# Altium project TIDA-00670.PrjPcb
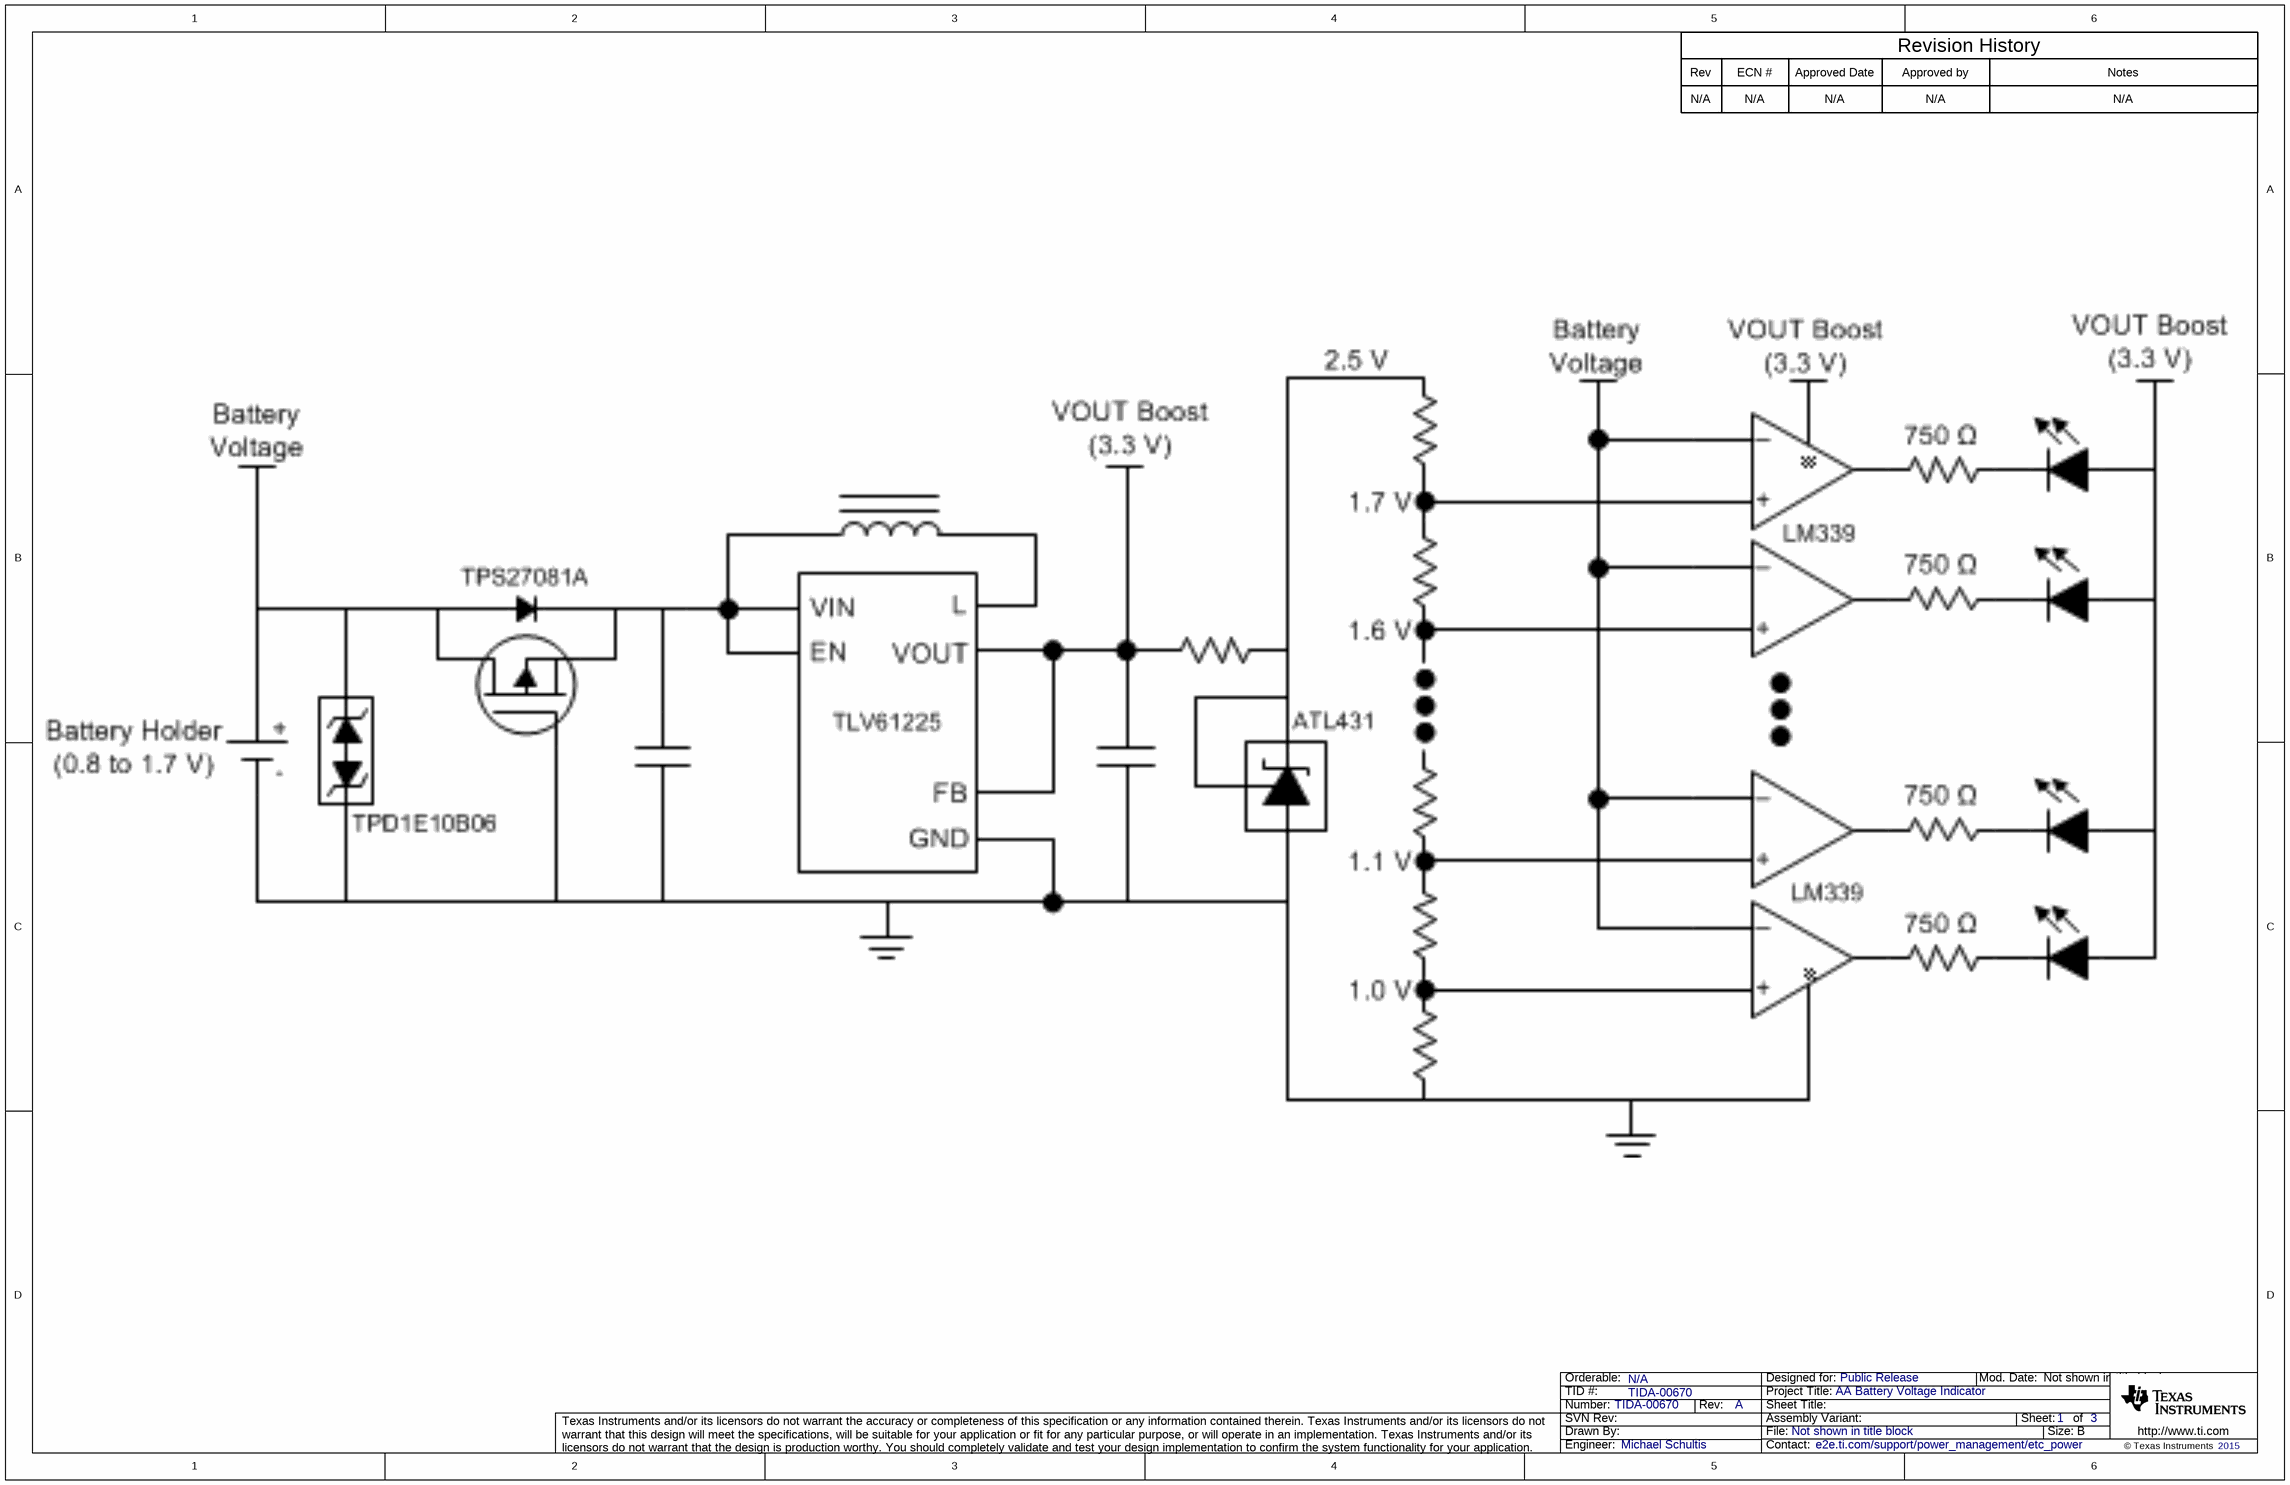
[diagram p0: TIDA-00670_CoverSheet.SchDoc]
TID: TIDA-00670; TechSupport: e2e.ti.com/support/power_management/etc_power; SCH_Rev: A; PRJ_Title: AA Battery Voltage Indicator; PRJ_Number: TIDA-00670; PRJ_Engineer: Michael Schultis; PRJ_Customer: Public Release; PCB_Rev: E1; PCB_Layout: Michael Schultis; EVM_Orderable: N/A; CopyrightYear: 2015
3 sheets, 54 parts. Net scope: global (net labels, ports and power ports of the same name join across sheets).
Board file: TIDA-00670_TID.PcbDoc
Sheets:
  TIDA-00670_CoverSheet.SchDoc
  TIDA-00670_BlankSheet.SchDoc
  TIDA-00670_TID_Hardware.SchDoc

## Sheet TIDA-00670_CoverSheet.SchDoc
size 431 x 279 mm; Date: Not shown in title block; ApprovedBy: Not shown in title block; CheckedBy: Not shown in title block; Author: Not shown in title block; CompanyName: Not shown in title block; Engineer: Not shown in title block; Organization: Not shown in title block; Address1: Not shown in title block; Address2: Not shown in title block; Address3: Not shown in title block; Address4: Not shown in title block; DocumentNumber: 1; Revision: Use project parameter SCH_Rev; SheetNumber: 1; SheetTotal: 3; PageSetup: Record=PageOptions¦CenterHorizontal=True¦CenterVertical=True¦PrintScale=1.00¦XCorrection=1.00¦YCorrection=1.00¦PrintKind=0¦BorderSize=5000000¦LeftOffset=0¦BottomOffset=0¦Orientation=2¦PaperLength=1000¦PaperWidth=1000¦Scale=100¦PaperSource=15¦PrintQuality=600¦MediaType=1¦DitherType=10¦PaperKind=Letter¦PrintScaleMode=1

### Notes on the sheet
- Rev
- N/A
- ECN #
- Approved Date
- Approved by
- Revision History
- Notes

## Sheet TIDA-00670_BlankSheet.SchDoc
size 431 x 279 mm; Date: Not shown in title block; ApprovedBy: Not shown in title block; CheckedBy: Not shown in title block; Author: Not shown in title block; CompanyName: Not shown in title block; Engineer: Not shown in title block; Organization: Not shown in title block; Address1: Not shown in title block; Address2: Not shown in title block; Address3: Not shown in title block; Address4: Not shown in title block; DocumentNumber: 1; Revision: Use project parameter SCH_Rev; SheetNumber: 2; SheetTotal: 3; PageSetup: Record=PageOptions¦CenterHorizontal=True¦CenterVertical=True¦PrintScale=1.00¦XCorrection=1.00¦YCorrection=1.00¦PrintKind=0¦BorderSize=5000000¦LeftOffset=0¦BottomOffset=0¦Orientation=2¦PaperLength=1000¦PaperWidth=1000¦Scale=100¦PaperSource=15¦PrintQuality=600¦MediaType=1¦DitherType=10¦PaperKind=Letter¦PrintScaleMode=1
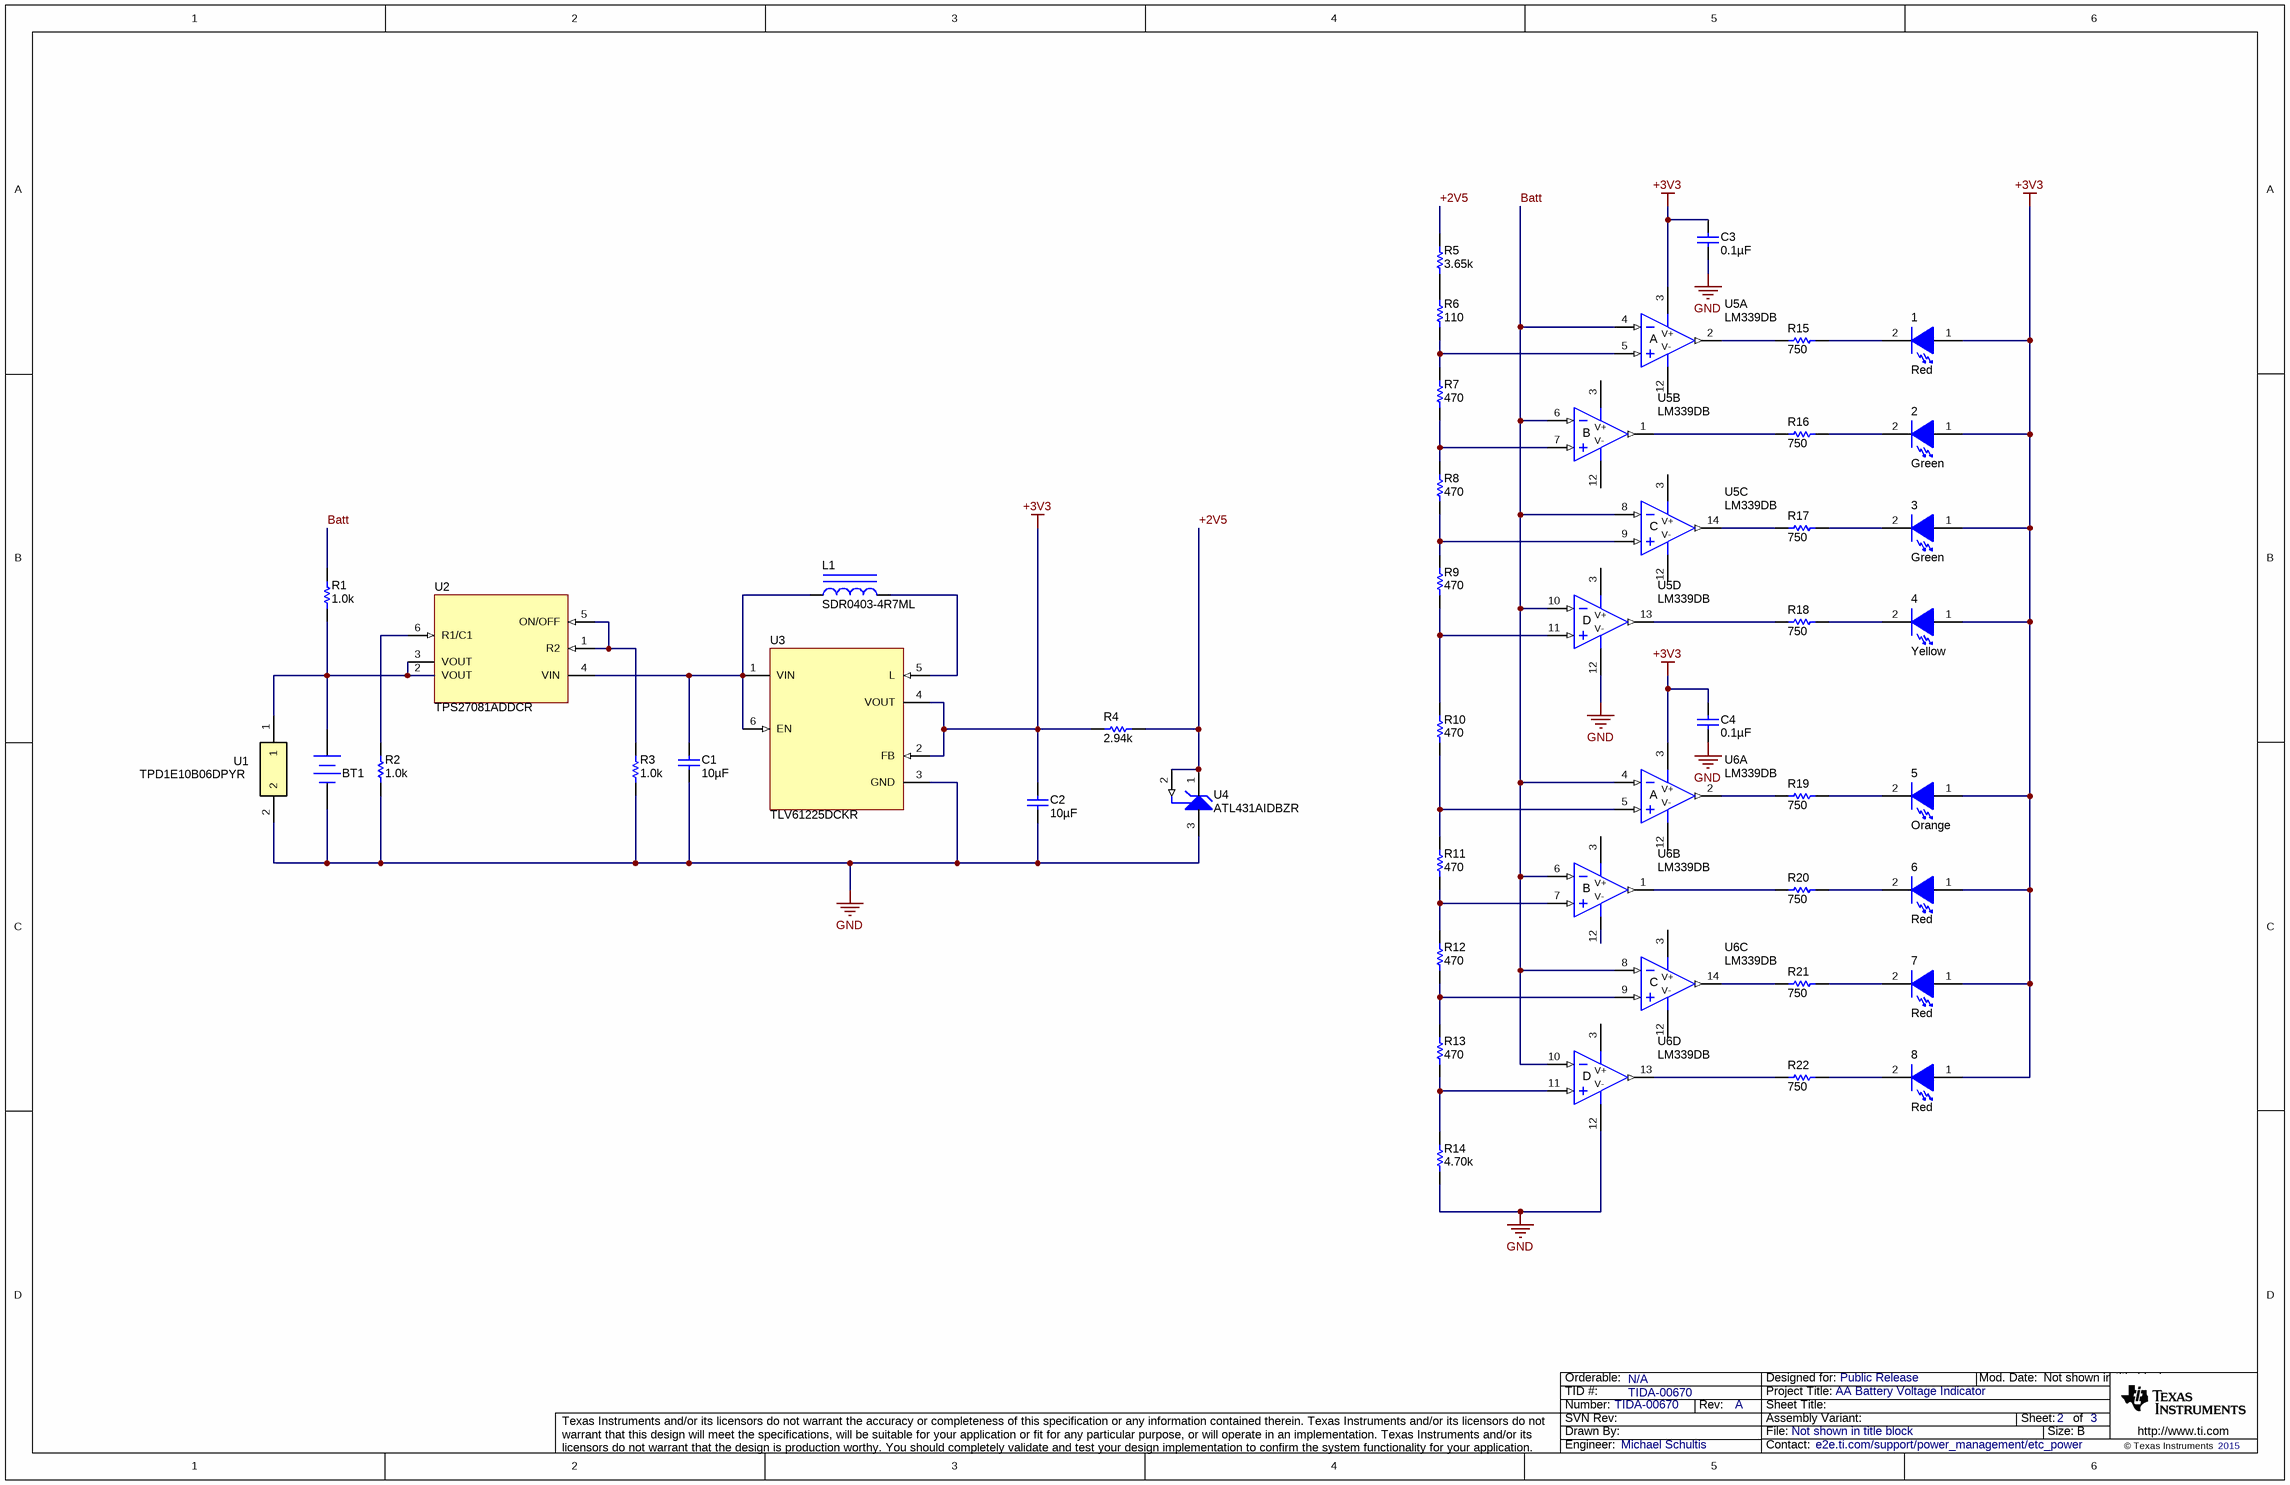
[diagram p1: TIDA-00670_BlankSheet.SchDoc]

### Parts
1  value Red  [LS L29K_Red]  (hidden comment: LS L29K-G1J2-1-Z)
2  value Green  [LG L29K_GREEN]  (hidden comment: LG L29K-G2J1-24-Z)
3  value Green  [LG L29K_GREEN]  (hidden comment: LG L29K-G2J1-24-Z)
4  value Yellow  [LY L29K_Yellow]  (hidden comment: LY L29K-H1K2-26-Z)
5  value Orange  [LO L29K_Orange]  (hidden comment: LO L29K-J2L1-24-Z)
6  value Red  [LS L29K_Red]  (hidden comment: LS L29K-G1J2-1-Z)
7  value Red  [LS L29K_Red]  (hidden comment: LS L29K-G1J2-1-Z)
8  value Red  [LS L29K_Red]  (hidden comment: LS L29K-G1J2-1-Z)
BT1  1015  [Keystone_1015]  (value not drawn)
C1  ValueDisplayed: 10µF  [0805_HV]  (hidden comment: C2012X5R0J106M)
C2  ValueDisplayed: 10µF  [0805_HV]  (hidden comment: C2012X5R0J106M)
C3  ValueDisplayed: 0.1µF  [0603]  (hidden comment: GRM188R70J104KA01D)
C4  ValueDisplayed: 0.1µF  [0603]  (hidden comment: GRM188R70J104KA01D)
L1  SDR0403-4R7ML  [SDR0403]
R1  ValueDisplayed: 1.0k  [0805_HV]  (hidden comment: ERJ-6GEYJ102V)
R2  ValueDisplayed: 1.0k  [0805_HV]  (hidden comment: ERJ-6GEYJ102V)
R3  ValueDisplayed: 1.0k  [0805_HV]  (hidden comment: ERJ-6GEYJ102V)
R4  ValueDisplayed: 2.94k  [0805_HV]  (hidden comment: ERJ-6ENF2941V)
R5  ValueDisplayed: 3.65k  [0805_HV]  (hidden comment: RR1220P-3651-D-M)
R6  ValueDisplayed: 110  [0805_HV]  (hidden comment: RR1220P-111-D)
R7  ValueDisplayed: 470  [0805_HV]  (hidden comment: RR1220P-471-D)
R8  ValueDisplayed: 470  [0805_HV]  (hidden comment: RR1220P-471-D)
R9  ValueDisplayed: 470  [0805_HV]  (hidden comment: RR1220P-471-D)
R10  ValueDisplayed: 470  [0805_HV]  (hidden comment: RR1220P-471-D)
R11  ValueDisplayed: 470  [0805_HV]  (hidden comment: RR1220P-471-D)
R12  ValueDisplayed: 470  [0805_HV]  (hidden comment: RR1220P-471-D)
R13  ValueDisplayed: 470  [0805_HV]  (hidden comment: RR1220P-471-D)
R14  ValueDisplayed: 4.70k  [0805_HV]  (hidden comment: RR1220P-472-D)
R15  ValueDisplayed: 750  [0805_HV]  (hidden comment: ERJ-6GEYJ751V)
R16  ValueDisplayed: 750  [0805_HV]  (hidden comment: ERJ-6GEYJ751V)
R17  ValueDisplayed: 750  [0805_HV]  (hidden comment: ERJ-6GEYJ751V)
R18  ValueDisplayed: 750  [0805_HV]  (hidden comment: ERJ-6GEYJ751V)
R19  ValueDisplayed: 750  [0805_HV]  (hidden comment: ERJ-6GEYJ751V)
R20  ValueDisplayed: 750  [0805_HV]  (hidden comment: ERJ-6GEYJ751V)
R21  ValueDisplayed: 750  [0805_HV]  (hidden comment: ERJ-6GEYJ751V)
R22  ValueDisplayed: 750  [0805_HV]  (hidden comment: ERJ-6GEYJ751V)
U1  TPD1E10B06DPYR  [DPY0002A]
U2  TPS27081ADDCR  [DDC0006A_N]
U3  TLV61225DCKR  [DCK0006A_N]
U4  ATL431AIDBZR  [DBZ0003A_N]
U5  LM339DB  [DB0014A_N]  (parts A,B,C,D of 4)
U6  LM339DB  [DB0014A_N]  (parts A,B,C,D of 4)

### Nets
+3V3: 1.1(A) 2.1(A) 3.1(A) 4.1(A) 5.1(A) 6.1(A) 7.1(A) 8.1(A) C2.1 C3.1 C4.1 R4.1 U3.2(FB) U3.4(VOUT) U5.3(V+) U6.3(V+)
GND: BT1.2(-) C1.2 C2.2 C3.2 C4.2 R2.1 R3.1 R14.1 U1.2 U3.3(GND) U4.3(ANODE) U5.12(V-) U6.12(V-)
+2V5: R4.2 R5.2 U4.1(CATHODE) U4.2(REF)
Batt: R1.2 U5.4(-IN1) U5.6(-IN2) U5.8(-IN3) U5.10(-IN4) U6.4(-IN1) U6.6(-IN2) U6.8(-IN3) U6.10(-IN4)
Net1_2: 1.2(K) R15.2
Net2_2: 2.2(K) R16.2
Net3_2: 3.2(K) R17.2
Net4_2: 4.2(K) R18.2
Net5_2: 5.2(K) R19.2
Net6_2: 6.2(K) R20.2
Net7_2: 7.2(K) R21.2
Net8_2: 8.2(K) R22.2
NetBT1_1: BT1.1(+) R1.1 U1.1 U2.2(VOUT) U2.3(VOUT)
NetC1_1: C1.1 L1.1 U2.4(VIN) U3.1(VIN) U3.6(EN)
NetL1_2: L1.2 U3.5(L)
NetR2_2: R2.2 U2.6(R1/C1)
NetR3_2: R3.2 U2.1(R2) U2.5(ON/OFF)
NetR5_1: R5.1 R6.2
NetR6_1: R6.1 R7.2 U5.5(+IN1)
NetR7_1: R7.1 R8.2 U5.7(+IN2)
NetR8_1: R8.1 R9.2 U5.9(+IN3)
NetR9_1: R9.1 R10.2 U5.11(+IN4)
NetR10_1: R10.1 R11.2 U6.5(+IN1)
NetR11_1: R11.1 R12.2 U6.7(+IN2)
NetR12_1: R12.1 R13.2 U6.9(+IN3)
NetR13_1: R13.1 R14.2 U6.11(+IN4)
NetR15_1: R15.1 U5.2(OUT1)
NetR16_1: R16.1 U5.1(OUT2)
NetR17_1: R17.1 U5.14(OUT3)
NetR18_1: R18.1 U5.13(OUT4)
NetR19_1: R19.1 U6.2(OUT1)
NetR20_1: R20.1 U6.1(OUT2)
NetR21_1: R21.1 U6.14(OUT3)
NetR22_1: R22.1 U6.13(OUT4)

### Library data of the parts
1 6-8 = LS L29K-G1J2-1-Z: LED, Red, SMD; Manufacturer: OSRAM; Vf_V: 1.8; Value2: 1.8V; Io_A: 0.02; Vr_V: 12; Tjmax_C: 110; Value1: W; Angle: 160; U/M: EA
2 3 = LG L29K-G2J1-24-Z: LED, Green, SMD; Manufacturer: OSRAM; Vf_V: 1.7; Value2: 1.7V; Io_A: 0.002; Tjmax_C: 110; Value1: W; U/M: EA
4 = LY L29K-H1K2-26-Z: LED, Yellow, SMD; Manufacturer: OSRAM; Vf_V: 1.8; Value2: 1.8V; Io_A: 0.02; Vr_V: 12; Tjmax_C: 110; Value1: W; Angle: 160; U/M: EA
5 = LO L29K-J2L1-24-Z: LED, Orange, SMD; Manufacturer: OSRAM; Vf_V: 1.8; Value2: 1.8V; Io_A: 0.02; Vr_V: 12; Tjmax_C: 110; Value1: W; Angle: 160; U/M: EA
BT1 = 1015: AA Battery Holder, Through-hole mount; Manufacturer: Keystone
C1 C2 = C2012X5R0J106M: CAP, CERM, 10 µF, 6.3 V, +/- 20%, X5R, 0805; Manufacturer: TDK; Polarized: N; CompType: Capacitor; Value: 10uF; U/M: EA; Cap_F: 0.00001; Tolerance_%: 20; ESR_ohm: 0.0026; Value1: 0.0026 ohm; VDC_V: 6.3; Value2: 6.3V; TaMin_C: -55; TaMax_C: 85; Cap_Case: 0805
C3 C4 = GRM188R70J104KA01D: CAP, CERM, 0.1 µF, 6.3 V, +/- 10%, X7R, 0603; Manufacturer: MuRata; Polarized: N; CompType: Capacitor; Value: 0.1uF; U/M: EA; Cap_F: 0.0000001; Tolerance_%: 10; Value1: Unknown; VDC_V: 6.3; Value2: 6.3V; TaMin_C: -55; TaMax_C: 125
L1 = SDR0403-4R7ML: Inductor, Drum Core, Ferrite, 4.7 µH, 1.7 A, 0.094 ohm, SMD; Manufacturer: Bourns; Value: 4.7uH; Ind_H: 4.7E-6; ValueDisplayed: 4.7µH; Imax_A: 1.7; Irms: 1.7A @ 40C rise; Isat: 2.47A @ 10% inductance drop; DCR_ohm: 0.094; Value2: 1.7A
R1-R3 = ERJ-6GEYJ102V: RES, 1.0 k, 5%, 0.125 W, 0805; Manufacturer: Panasonic; CompType: Resistor; Value: 1.0k; Res_ohm: 1000; Value_Code: 1k00; Tolerance_%: 5; Power_W: 0.125; Value2: 0.125W; VDC_V: 150; TempCo: 200 ppm/C; EIA_Code: E24; U/M: EA
R4 = ERJ-6ENF2941V: RES, 2.94 k, 1%, 0.125 W, 0805; Manufacturer: Panasonic; CompType: Resistor; Value: 2.94k; Res_ohm: 2940; Value_Code: 2k94; Tolerance_%: 1; Power_W: 0.125; Value2: 0.125W; TempCo: 100 ppm/C; EIA_Code: E96; U/M: EA
R5 = RR1220P-3651-D-M: RES, 3.65 k, 0.5%, 0.1 W, 0805; Manufacturer: Susumu Co Ltd; CompType: Resistor; Value: 3.65k; Res_ohm: 3650; Value_Code: 3k65; Tolerance_%: 0.5; Power_W: 0.1; Value2: 0.1W; VDC_V: 100; TempCo: 25 ppm/C; EIA_Code: E192; U/M: EA
R6 = RR1220P-111-D: RES, 110, 0.5%, 0.1 W, 0805; Manufacturer: Susumu Co Ltd; CompType: Resistor; Value: 110; Value_Code: 110R; Tolerance_%: 0.5; Power_W: 0.1; Value2: 0.1W; VDC_V: 100; TempCo: 25 ppm/C; EIA_Code: E192; U/M: EA
R7-R13 = RR1220P-471-D: RES, 470, 0.5%, 0.1 W, 0805; Manufacturer: Susumu Co Ltd; CompType: Resistor; Value: 470; Value_Code: 470R; Tolerance_%: 0.5; Power_W: 0.1; Value2: 0.1W; VDC_V: 100; TempCo: 25 ppm/C; EIA_Code: E192; U/M: EA
R14 = RR1220P-472-D: RES, 4.70 k, 0.5%, 0.1 W, 0805; Manufacturer: Susumu Co Ltd; CompType: Resistor; Value: 4.70k; Res_ohm: 4700; Value_Code: 4k70; Tolerance_%: 0.5; Power_W: 0.1; Value2: 0.1W; VDC_V: 100; TempCo: 25 ppm/C; EIA_Code: E192; U/M: EA
R15-R22 = ERJ-6GEYJ751V: RES, 750, 5%, 0.125 W, 0805; Manufacturer: Panasonic; CompType: Resistor; Value: 750; Value_Code: 750R; Tolerance_%: 5; Power_W: 0.125; Value2: 0.125W; VDC_V: 150; TempCo: 200 ppm/C; EIA_Code: E24; U/M: EA
U1 = TPD1E10B06DPYR: ESD in 0402 Package with 10 pF Capacitance and 6 V Breakdown, 1 Channel, -40 to +125 degC, 2-pin X2SON (DPY), Green (RoHS & no Sb/Br); Manufacturer: Texas Instruments; Alternate PartNumber: Equivalent; Breakdown Voltage(Min)(V): 6; Eco-Plan: TBD; IEC 61000-4-2 Air-Gap(+/- kV): 30; IO Capacitance(Typ)(pF): 10; SubFamily: ESD Solution
U2 = TPS27081ADDCR: 1.2V - 8V, 3A PFET High Side Load Switch with Level Shift & Adjustable Slew Rate Control, DDC0006A; Manufacturer: Texas Instruments; SymbolCreator: a0411947; CompType: IC; U/M: EA
U3 = TLV61225DCKR: SINGLE CELL HIGH EFFICIENT STEP-UP CONVERTER, DCK0006A; Alternate PartNumber: TLV61225DCKT; Manufacturer: Texas Instruments; SymbolCreator: Altium; CompType: IC; U/M: EA
U4 = ATL431AIDBZR: 2.5V Low Iq Adjustable Precision Shunt Regulator, DBZ0003A; Manufacturer: Texas Instruments; SymbolCreator: a0412235; CompType: IC; U/M: EA
U5 U6 = LM339DB: Quad Comparator, DB0014A; Manufacturer: Texas Instruments; SymbolCreator: Altium; CompType: OpAmp IC

## Sheet TIDA-00670_TID_Hardware.SchDoc
size 431 x 279 mm; Date: Not shown in title block; ApprovedBy: Not shown in title block; CheckedBy: Not shown in title block; Author: Not shown in title block; CompanyName: Not shown in title block; Engineer: Not shown in title block; Organization: Not shown in title block; Address1: Not shown in title block; Address2: Not shown in title block; Address3: Not shown in title block; Address4: Not shown in title block; DocumentNumber: 1; Revision: Use project parameter SCH_Rev; SheetNumber: 3; SheetTotal: 3; PageSetup: Record=PageOptions¦CenterHorizontal=True¦CenterVertical=True¦PrintScale=1.00¦XCorrection=1.00¦YCorrection=1.00¦PrintKind=0¦BorderSize=5000000¦LeftOffset=0¦BottomOffset=0¦Orientation=2¦PaperLength=1000¦PaperWidth=1000¦Scale=100¦PaperSource=15¦PrintQuality=600¦MediaType=1¦DitherType=10¦PaperKind=Letter¦PrintScaleMode=1
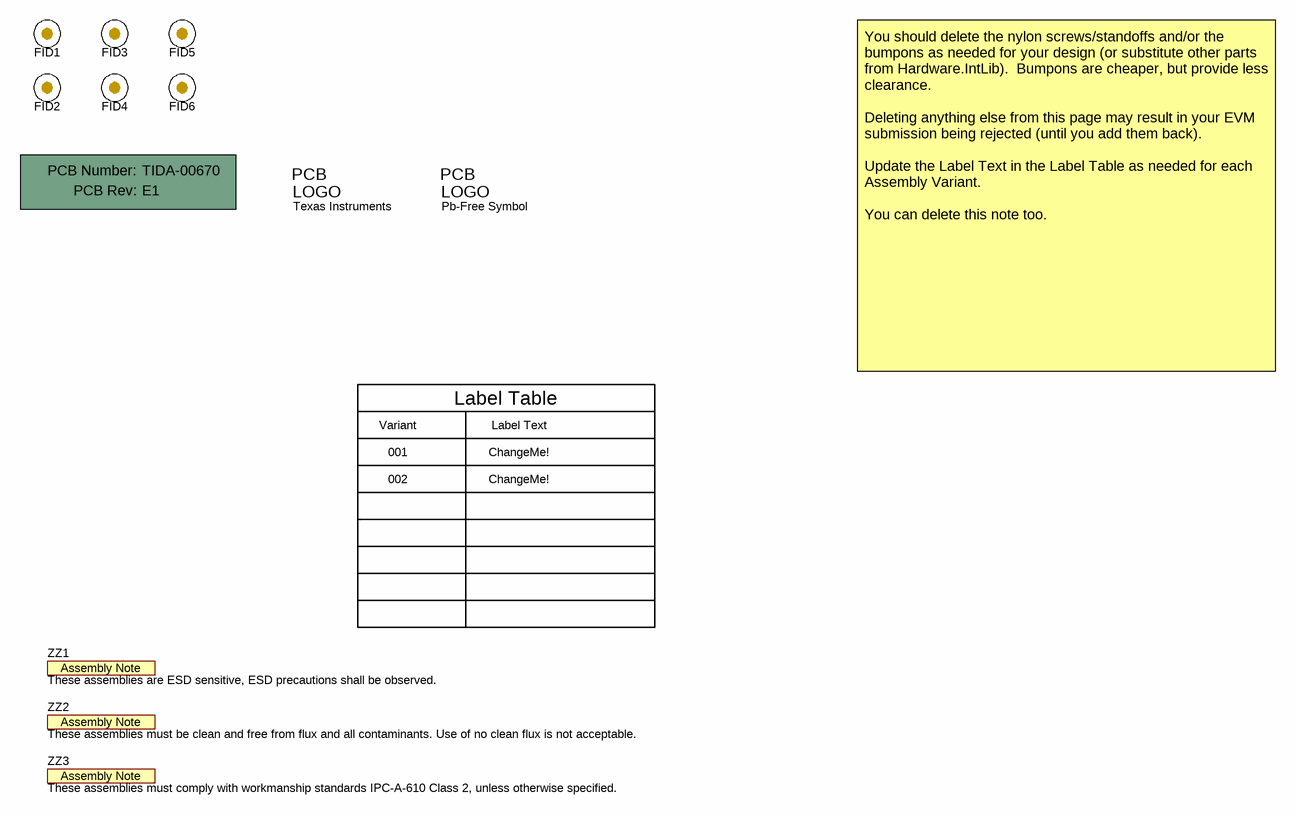
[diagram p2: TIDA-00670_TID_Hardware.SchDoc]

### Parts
!PCB1  Printed Circuit Board  (value not drawn)  (mechanical)
FID1  Fiducial  [Fiducial10-20]  (value not drawn)
FID2  Fiducial  [Fiducial10-20]  (value not drawn)
FID3  Fiducial  [Fiducial10-20]  (value not drawn)
FID4  Fiducial  [Fiducial10-20]  (value not drawn)
FID5  Fiducial  [Fiducial10-20]  (value not drawn)
FID6  Fiducial  [Fiducial10-20]  (value not drawn)
Logo1  Texas Instruments  [TI_Stacked_Overlay_Small]  (no BOM)
Logo2  Pb-Free Symbol  [Pb-Free_Overlay_Small]  (no BOM)
ZZ1  These assemblies are ESD sensitive, ESD precautions shall be observed.  [AssemblyNote]  (no BOM)
ZZ2  These assemblies must be clean and free from flux and all contaminants. Use of no clean flux is not acceptable.  [AssemblyNote]  (no BOM)
ZZ3  These assemblies must comply with workmanship standards IPC-A-610 Class 2, unless otherwise specified.  [AssemblyNote]  (no BOM)

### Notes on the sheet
- Variant
- Label Table
- Label Text
- You should delete the nylon screws/standoffs and/or the bumpons as needed for your design (or substitute other parts from Hardware.IntLib).  Bumpons are cheaper, but provide less clearance.
  Deleting anything else from this page may result in your EVM submission being rejected (until you add them back).
  Update the Label Text in the Label Table as needed for each Assembly Variant.
  You can delete this note too.
- 001
- 002
- ChangeMe!

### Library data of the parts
!PCB1 = PCB: Manufacturer: Any; PartNumber: TIDA-00670; SymbolCreator: a0412235
FID1-FID6 = Fiducial: Fiducial mark.  There is nothing to buy or mount.; SymbolCreator: codlsc
Logo1 = TI_Logo: Texas Instrument Corporate Signature; SymbolCreator: codlsc
Logo2 = Pb-Free: SymbolCreator: a0412235
ZZ1-ZZ3 = AssemblyNote: SymbolCreator: codlsc

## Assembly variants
001: not fitted FID1 FID2 FID3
